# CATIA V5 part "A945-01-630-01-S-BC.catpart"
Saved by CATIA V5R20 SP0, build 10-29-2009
Part number: A945-01-630-01-S-BC
Source: Unknown
Property "ARTICLENO": "A945-01-630-01-S-BC"
Property "B": "65.000"
Property "BOMINFO": "A945-01-630-01-S-BC"
Property "CODE": "A945-01-630-01-S-BC"
Property "D1": "20.000"
Property "D2": "13.500"
Property "D5": "16.000"
Property "D6": "12.000"
Property "H": "47.000"
Property "H1": "34.000"
Property "H2": "35.000"
Property "H3": "18.000"
Property "L1": "300.000"
Property "L2": "25.000"
Property "L3": "125.000"
Property "L4": "125.000"
Property "L5": "55.000"
Property "L6": "195.000"
Property "LINA": "A945-01-630-01-S-BC"
Property "N": "4.000"
Property "NB": "A945-01-630-01-S-BC"
Property "NBSYN": " $CODE."
Property "NN": "A945-01"
Property "NT": "v driver sets replaceable inserts pisitive return"
Property "SUPPLIER": "CF"
Property "Z": "65.000"
Bounding box of the stored display mesh (mm): x -5049.207 to -4951.207, y -575.36 to -510.36, z 0 to 300
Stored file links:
  C:\Users\Utente\Desktop\3D files A945-01\A945-01-630-01-S-BC.catpart
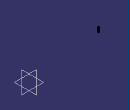
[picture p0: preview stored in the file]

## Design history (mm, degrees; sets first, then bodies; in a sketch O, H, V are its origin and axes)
Body1 "Geometry.1" (main body)
  Solid1 "A945-01-630-01-S-BC.catpart": solid without history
